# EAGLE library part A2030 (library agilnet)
ADNS-2030 Optical Mouse Sensor from Agilent Technologies
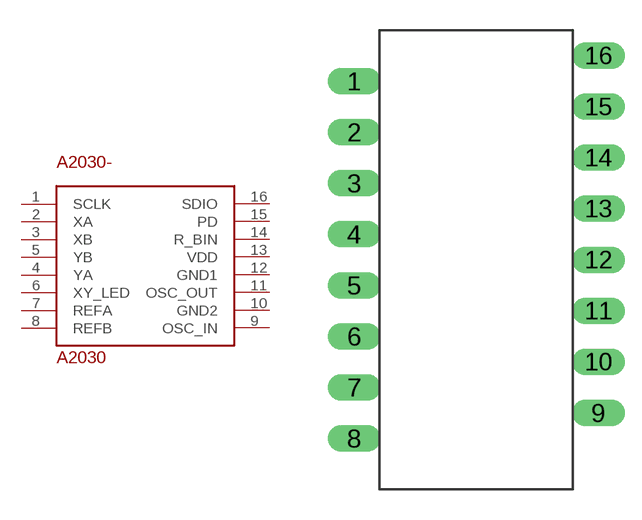
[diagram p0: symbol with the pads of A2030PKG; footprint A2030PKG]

Designator prefix A2030-

## A2030DIP  [A2030PKG]
1  SCLK
2  XA
3  XB
4  YA
5  YB
6  XY_LED
7  REFA
8  REFB
9  OSC_IN
10  GND2  pwr
11  OSC_OUT
12  GND1  pwr
13  VDD  pwr
14  R_BIN
15  PD
16  SDIO

## Footprint A2030PKG (pad centres in mm)
ADNS-2030 Optical Mouse Sensor DIP version
drill 0.813 long: 1 -6.08,10.16; 2 -6.08,7.62; 3 -6.08,5.08; 4 -6.08,2.54; 5 -6.08,0; 6 -6.08,-2.54; 7 -6.08,-5.08; 8 -6.08,-7.62; 9 6.08,-6.35; 10 6.08,-3.81; 11 6.08,-1.27; 12 6.08,1.27; 13 6.08,3.81; 14 6.08,6.35; 15 6.08,8.89; 16 6.08,11.43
